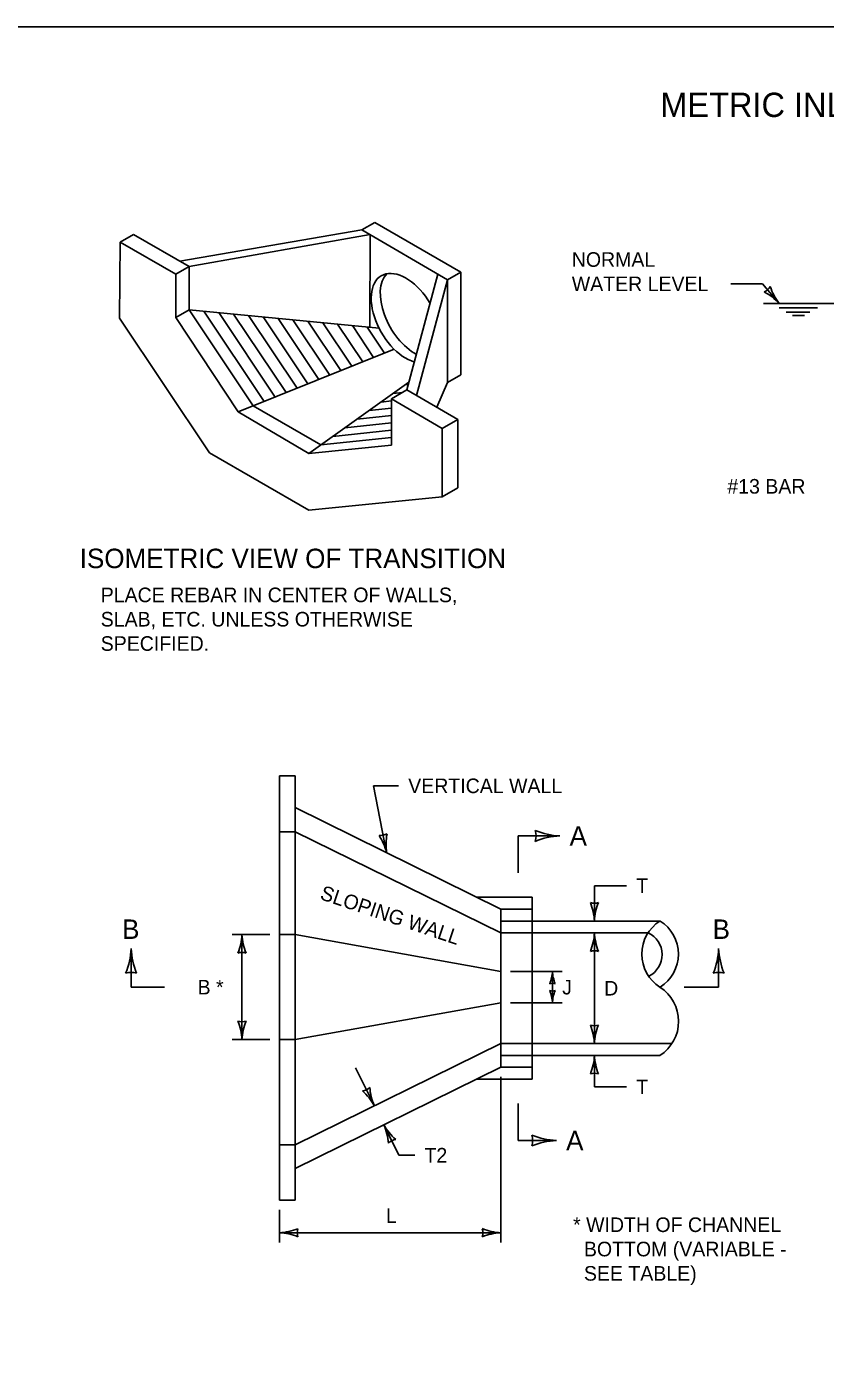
# Model space of a CAD drawing. Extents: x 49991.4 to 50043, y 49987.6 to 50011.4.
# Drawn here: x 50008.63 to 50011.91, y 49993.47 to 49999 of the extents above; entities that cross this region are included whole.
import ezdxf

# ---------------------------------------------------------------- set-up
doc = ezdxf.new("R2010")
doc.units = 0
for name, color, linetype in [('Level 1', 7, 'Continuous'), ('Level 2', 7, 'Continuous'), ('Level 3', 7, 'Continuous'), ('Level 4', 7, 'Continuous'), ('Level 6', 7, 'Continuous')]:
    doc.layers.add(name, color=color, linetype=linetype)

msp = doc.modelspace()

# ---------------------------------------------------------------- linework, layer by layer
at = {"layer": 'Level 1'}
for p, q in [((50009.012, 49998.1146), (50009.0665, 49998.1461)), ((50009.2955, 49998.0139), (50009.0665, 49998.1461)), ((50010.0065, 49998.1648), (50009.2575, 49998.0359)), ((50010.0402, 49998.1451), (50009.2955, 49998.0139)), ((50010.0596, 49998.1956), (50010.0064, 49998.1648)), ((50010.0064, 49998.1648), (50010.359, 49997.9596)), ((50010.0402, 49998.1451), (50010.039, 49997.7642)), ((50010.4135, 49997.9911), (50010.0596, 49998.1956)), ((50009.012, 49998.1146), (50009.0099, 49997.8017)), ((50009.241, 49997.9824), (50009.012, 49998.1146)), ((50009.241, 49997.9824), (50009.2955, 49998.0139)), ((50009.241, 49997.9824), (50009.241, 49997.8046)), ((50009.2955, 49998.0139), (50009.2955, 49997.8361)), ((50010.1915, 49997.5066), (50010.3193, 49997.9827)), ((50010.359, 49997.9596), (50010.4135, 49997.9911)), ((50010.4135, 49997.9911), (50010.4135, 49997.5687)), ((50010.2313, 49997.4834), (50010.359, 49997.9596)), ((50010.359, 49997.5372), (50010.359, 49997.9596)), ((50009.241, 49997.8046), (50009.2955, 49997.8361)), ((50009.2955, 49997.8361), (50009.5594, 49997.4411)), ((50009.2955, 49997.8361), (50010.077, 49997.7605)), ((50009.3566, 49997.8302), (50009.6044, 49997.4592)), ((50009.4176, 49997.8243), (50009.6494, 49997.4773)), ((50009.4787, 49997.8184), (50009.6945, 49997.4954)), ((50009.5397, 49997.8125), (50009.7395, 49997.5135)), ((50011.6575, 49997.8625), (50011.9879, 49997.8625)), ((50011.7227, 49997.8436), (50011.8806, 49997.8436)), ((50011.7519, 49997.8265), (50011.8489, 49997.8265)), ((50011.7768, 49997.8123), (50011.8263, 49997.8123)), ((50009.0099, 49997.8017), (50009.3799, 49997.248)), ((50009.241, 49997.8046), (50009.498, 49997.4164)), ((50009.6008, 49997.8066), (50009.7845, 49997.5316)), ((50009.6619, 49997.8007), (50009.8295, 49997.5497)), ((50009.7229, 49997.7948), (50009.8746, 49997.5678)), ((50009.784, 49997.7889), (50009.9196, 49997.5859)), ((50009.845, 49997.783), (50009.9646, 49997.604)), ((50009.9061, 49997.7771), (50010.0096, 49997.622)), ((50009.9672, 49997.7712), (50010.0547, 49997.6401)), ((50010.0282, 49997.7652), (50010.0997, 49997.6582)), ((50009.498, 49997.4164), (50010.1391, 49997.6741)), ((50009.788, 49997.2452), (50010.1999, 49997.5378)), ((50010.359, 49997.5372), (50010.3142, 49997.4351)), ((50010.4135, 49997.5687), (50010.359, 49997.5372)), ((50010.1915, 49997.5066), (50010.1285, 49997.4702)), ((50010.1728, 49997.4958), (50010.1352, 49997.4919)), ((50010.1974, 49997.5285), (50010.1848, 49997.5271)), ((50010.1915, 49997.5066), (50010.4003, 49997.3849)), ((50009.5594, 49997.4411), (50009.8376, 49997.2805)), ((50010.1285, 49997.4311), (50010.036, 49997.4214)), ((50010.1285, 49997.4611), (50010.0856, 49997.4567)), ((50010.1285, 49997.4702), (50010.1285, 49997.2791)), ((50010.1285, 49997.4702), (50010.3367, 49997.3483)), ((50009.498, 49997.4164), (50009.788, 49997.2452)), ((50010.1285, 49997.371), (50009.9368, 49997.3509)), ((50010.1285, 49997.401), (50009.9864, 49997.3862)), ((50010.4003, 49997.3849), (50010.3367, 49997.3483)), ((50010.4003, 49997.3849), (50010.4003, 49997.1042)), ((50010.1285, 49997.3409), (50009.8872, 49997.3157)), ((50010.3367, 49997.3483), (50010.3367, 49997.0674)), ((50010.1285, 49997.2791), (50009.788, 49997.2452)), ((50010.1285, 49997.3108), (50009.8376, 49997.2805)), ((50009.7887, 49997.012), (50009.3799, 49997.248)), ((50010.4003, 49997.1042), (50010.3367, 49997.0674)), ((50010.3367, 49997.0674), (50009.7887, 49997.012)), ((50009.7322, 49995.9197), (50009.6672, 49995.9197)), ((50009.6672, 49995.9197), (50009.6672, 49994.1757)), ((50009.7322, 49994.1757), (50009.7322, 49995.9197)), ((50010.5772, 49995.3715), (50009.7322, 49995.7897)), ((50009.7322, 49995.6898), (50009.6672, 49995.6898)), ((50010.5772, 49995.274), (50009.7322, 49995.6898)), ((50010.7072, 49995.4203), (50010.4786, 49995.4203)), ((50010.7072, 49995.4203), (50010.7072, 49994.6728)), ((50010.5772, 49994.7215), (50010.5772, 49995.3715)), ((50011.2324, 49995.3228), (50010.5772, 49995.3228)), ((50009.7322, 49995.2668), (50009.6672, 49995.2668)), ((50009.7322, 49995.2668), (50010.5772, 49995.1159)), ((50009.7322, 49994.835), (50010.5772, 49994.9859)), ((50009.7322, 49994.835), (50009.6672, 49994.835)), ((50010.5772, 49994.819), (50009.7322, 49994.4032)), ((50011.2324, 49994.7703), (50010.5772, 49994.7703)), ((50010.5772, 49994.7215), (50009.7322, 49994.3057)), ((50010.7072, 49994.6728), (50010.4782, 49994.6728)), ((50009.7322, 49994.4032), (50009.6672, 49994.4032)), ((50009.6672, 49994.1757), (50009.7322, 49994.1757))]:
    msp.add_line(p, q, dxfattribs=at)
msp.add_lwpolyline([(49999.3835, 49998.9992), (50016.7501, 49998.9992), (50016.7501, 49987.7988), (49999.3835, 49987.7988)], close=True, dxfattribs=at)
for centre, radius, start, end in [((50011.3184, 49995.1868), 0.1609, 122.3335, 237.6665), ((50011.1423, 49995.1842), 0.0988, 296.2298, 65.513), ((50011.1482, 49995.1868), 0.1599, 301.772, 58.228), ((50011.1422, 49994.9106), 0.1667, 302.7325, 57.2885)]:
    msp.add_arc(centre, radius, start, end, dxfattribs=at)
for centre, start_param, end_param in [((50010.1874, 49997.8013), 4.726836, 8.88612), ((50010.2246, 49997.8211), 0.161802, 2.399384)]:
    msp.add_ellipse(centre, major_axis=(-0.101, 0.1749), ratio=0.57735, start_param=start_param, end_param=end_param, dxfattribs=at)
at = {"layer": 'Level 3'}
for p, q in [((50011.6537, 49997.9428), (50011.5238, 49997.9428)), ((50011.7225, 49997.8625), (50011.6537, 49997.9428)), ((50010.0537, 49995.8787), (50010.1569, 49995.8787)), ((50010.1081, 49995.6037), (50010.0537, 49995.8787)), ((50010.9627, 49995.3228), (50010.9627, 49995.468)), ((50010.9627, 49995.468), (50011.0945, 49995.468)), ((50010.9627, 49995.274), (50010.9627, 49994.819)), ((50009.6272, 49995.2668), (50009.473, 49995.2668)), ((50009.513, 49995.2668), (50009.513, 49994.835)), ((50010.6172, 49995.1159), (50010.8301, 49995.1159)), ((50010.7901, 49995.1159), (50010.7901, 49994.9859)), ((50010.6172, 49994.9859), (50010.8301, 49994.9859)), ((50009.6272, 49994.835), (50009.473, 49994.835)), ((50010.9627, 49994.7703), (50010.9627, 49994.6409)), ((50009.9804, 49994.7187), (50010.0576, 49994.5633)), ((50010.5772, 49994.6815), (50010.5772, 49994.001)), ((50010.9627, 49994.6409), (50011.0945, 49994.6409)), ((50010.0965, 49994.485), (50010.1587, 49994.3599)), ((50010.1587, 49994.3599), (50010.2237, 49994.3599)), ((50009.6672, 49994.1357), (50009.6672, 49994.001)), ((50009.6672, 49994.041), (50010.5772, 49994.041))]:
    msp.add_line(p, q, dxfattribs=at)
for centre, radius, start, end in [((50011.6391, 49997.9599), 0.0548, 292.7196, 328.442), ((50011.9068, 49998.0052), 0.233, 198.5036, 217.7535), ((50011.5598, 49997.7111), 0.2223, 42.9413, 63.1248), ((50010.0832, 49995.7295), 0.0548, 263.3245, 299.0469), ((50009.882, 49995.5473), 0.233, 14.013, 33.2629), ((50010.3278, 49995.6378), 0.2223, 168.6417, 188.8252), ((50010.8328, 49995.969), 0.2964, 247.456, 267.6395), ((50010.6497, 49995.6728), 0.073, 342.1388, 17.8612), ((50010.8359, 49995.3625), 0.3107, 92.8273, 112.0772), ((50010.9627, 49995.451), 0.0548, 252.1388, 287.8612), ((50010.73, 49995.3113), 0.233, 2.8273, 22.0772), ((50011.1848, 49995.3137), 0.2223, 157.456, 177.6395), ((50010.7406, 49995.2832), 0.2223, 337.456, 357.6395), ((50011.1954, 49995.2855), 0.233, 182.8273, 202.0772), ((50009.2909, 49995.276), 0.2223, 337.456, 357.6395), ((50009.7457, 49995.2783), 0.233, 182.8273, 202.0772), ((50008.761, 49995.2215), 0.2964, 337.456, 357.6395), ((50009.3675, 49995.2246), 0.3107, 182.8273, 202.0772), ((50009.513, 49995.1386), 0.0548, 72.1388, 107.8612), ((50010.9627, 49995.1458), 0.0548, 72.1388, 107.8612), ((50011.1774, 49995.2215), 0.2964, 337.456, 357.6395), ((50011.7839, 49995.2246), 0.3107, 182.8273, 202.0772), ((50009.0572, 49995.0384), 0.073, 72.1388, 107.8612), ((50010.642, 49995.122), 0.1482, 337.456, 357.6395), ((50010.9452, 49995.1236), 0.1553, 182.8273, 202.0772), ((50011.4736, 49995.0384), 0.073, 72.1388, 107.8612), ((50010.7901, 49995.0304), 0.0365, 72.1388, 107.8612), ((50010.7901, 49995.0714), 0.0365, 252.1388, 287.8612), ((50010.635, 49994.9783), 0.1553, 2.8273, 22.0772), ((50010.9382, 49994.9798), 0.1482, 157.456, 177.6395), ((50009.513, 49994.9632), 0.0548, 252.1388, 287.8612), ((50009.2803, 49994.8235), 0.233, 2.8273, 22.0772), ((50009.7351, 49994.8259), 0.2223, 157.456, 177.6395), ((50010.9627, 49994.9472), 0.0548, 252.1388, 287.8612), ((50010.73, 49994.8075), 0.233, 2.8273, 22.0772), ((50011.1848, 49994.8099), 0.2223, 157.456, 177.6395), ((50010.7406, 49994.7795), 0.2223, 337.456, 357.6395), ((50011.1954, 49994.7818), 0.233, 182.8273, 202.0772), ((50010.9627, 49994.6421), 0.0548, 72.1388, 107.8612), ((50010.0005, 49994.6782), 0.0548, 278.5638, 314.2861), ((50009.8543, 49994.4495), 0.233, 29.2523, 48.5021), ((50010.2606, 49994.654), 0.2223, 183.881, 204.0645), ((50009.8935, 49994.3943), 0.2223, 3.8914, 24.0749), ((50010.2998, 49994.5989), 0.233, 209.2627, 228.5126), ((50010.8186, 49994.7165), 0.2964, 247.456, 267.6395), ((50010.6355, 49994.4203), 0.073, 342.1388, 17.8612), ((50010.1536, 49994.3702), 0.0548, 98.5742, 134.2966), ((50010.8217, 49994.11), 0.3107, 92.8273, 112.0772), ((50009.6557, 49994.2737), 0.233, 272.8273, 292.0772), ((50009.7954, 49994.041), 0.0548, 162.1388, 197.8612), ((50010.5864, 49994.2632), 0.2223, 247.456, 267.6395), ((50010.449, 49994.041), 0.0548, 342.1388, 17.8612), ((50009.658, 49993.8189), 0.2223, 67.456, 87.6395), ((50010.5887, 49993.8083), 0.233, 92.8273, 112.0772)]:
    msp.add_arc(centre, radius, start, end, dxfattribs=at)
at = {"layer": 'Level 4'}
for p, q in [((50010.5772, 49995.3715), (50010.7072, 49995.3715)), ((50011.1832, 49995.274), (50010.5772, 49995.274)), ((50011.2816, 49994.819), (50010.5772, 49994.819)), ((50010.5772, 49994.7215), (50010.7072, 49994.7215))]:
    msp.add_line(p, q, dxfattribs=at)
at = {"layer": 'Level 6'}
for p, q in [((50010.6491, 49995.6728), (50010.8206, 49995.6728)), ((50010.6491, 49995.5203), (50010.6491, 49995.6728)), ((50009.0572, 49995.0509), (50009.0572, 49995.2093)), ((50011.4736, 49995.0509), (50011.4736, 49995.2093)), ((50009.0572, 49995.0509), (50009.1944, 49995.0509)), ((50011.3324, 49995.0509), (50011.4736, 49995.0509)), ((50010.6491, 49994.4203), (50010.6491, 49994.5728)), ((50010.6491, 49994.4203), (50010.8064, 49994.4203))]:
    msp.add_line(p, q, dxfattribs=at)

# ---------------------------------------------------------------- texts
at = {"layer": 'Level 2'}
for s, height, p in [('METRIC INLET AND OUTLET TRANSITION', 0.1, (50011.2338, 49998.6287)), ('NORMAL', 0.06, (50010.8696, 49998.0128)), ('WATER LEVEL', 0.06, (50010.8696, 49997.9128)), ('#13 BAR', 0.06, (50011.5094, 49997.0802)), ('ISOMETRIC VIEW OF TRANSITION', 0.08, (50008.8459, 49996.7738)), ('PLACE REBAR IN CENTER OF WALLS,', 0.06, (50008.9322, 49996.6338)), ('SLAB, ETC. UNLESS OTHERWISE', 0.06, (50008.9322, 49996.5338)), ('SPECIFIED.', 0.06, (50008.9322, 49996.4338)), ('VERTICAL WALL', 0.06, (50010.1969, 49995.8487)), ('A', 0.0799, (50010.8606, 49995.6329)), ('T', 0.06, (50011.1345, 49995.438)), ('B', 0.0799, (50009.0202, 49995.2493)), ('B', 0.0799, (50011.4488, 49995.2493)), ('B *', 0.06, (50009.3305, 49995.0209)), ('J', 0.06, (50010.8301, 49995.0209)), ('D', 0.06, (50011.0027, 49995.0165)), ('T', 0.06, (50011.1345, 49994.6109)), ('A', 0.0799, (50010.8464, 49994.3803)), ('T2', 0.06, (50010.2637, 49994.3299)), ('L', 0.06, (50010.1052, 49994.081)), ('* WIDTH OF CHANNEL', 0.06, (50010.8749, 49994.0441)), ('  BOTTOM (VARIABLE -', 0.06, (50010.8749, 49993.9441)), ('  SEE TABLE)', 0.06, (50010.8749, 49993.8441))]:
    msp.add_text(s, height=height, dxfattribs=at).set_placement(p)
msp.add_text('SLOPING WALL', height=0.06, rotation=341.4654, dxfattribs=at).set_placement((50009.8303, 49995.4137))

doc.saveas('drawing.dxf')
